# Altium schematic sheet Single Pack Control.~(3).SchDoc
size A
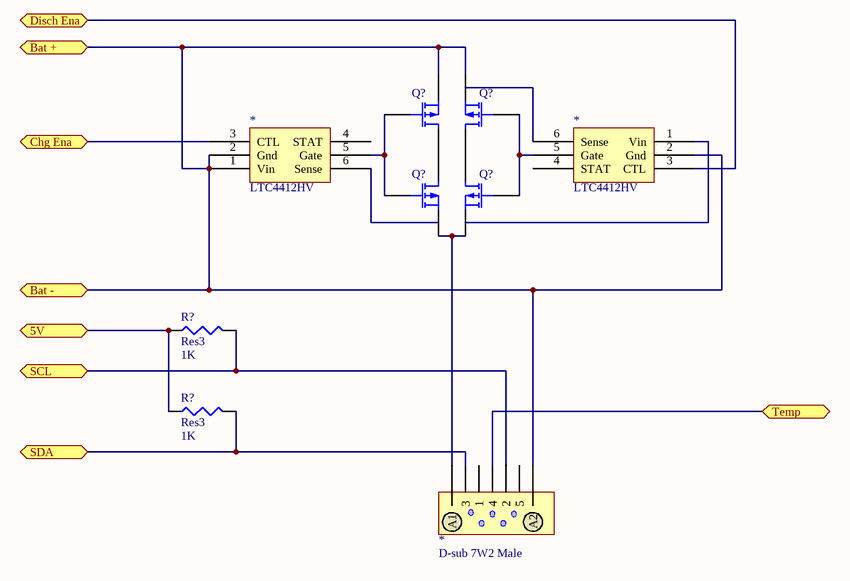
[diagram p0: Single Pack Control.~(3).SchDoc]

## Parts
(Parts that share a designator on the sheet are numbered #1, #2 ... from top to bottom, then left to right.)
*#1  LTC4412HV
*#2  LTC4412HV
*#3  D-sub 7W2 Male
Q?#1  MOSFET-P  [BCY-W3/B.8]  (value not drawn)
Q?#2  MOSFET-P  [BCY-W3/B.8]  (value not drawn)
Q?#3  MOSFET-P  [BCY-W3/B.8]  (value not drawn)
Q?#4  MOSFET-P  [BCY-W3/B.8]  (value not drawn)
R?#1  Res3  value 1K  [RESC1608L]
R?#2  Res3  value 1K  [RESC1608L]

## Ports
5V, Bat +, Bat -, Chg Ena, Disch Ena, SCL, SDA, Temp

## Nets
5V: R?#1.1 R?#2.1 ; port 5V
Bat +: *#1.1(Vin) *#1.2(Gnd) *#2.2(Gnd) *#3.7(A2) Q?#1.3(S) Q?#2.3(S) ; port Bat +, port Bat -
Chg Ena: *#1.3(CTL) ; port Chg Ena
Disch Ena: *#2.3(CTL) ; port Disch Ena
SCL: *#3.2 R?#1.2 ; port SCL
SDA: *#3.3 R?#2.2 ; port SDA
Temp: *#3.4 ; port Temp
Net*#1_5: *#1.5(Gate) Q?#1.2(G) Q?#3.2(G)
Net*#2_5: *#2.5(Gate) Q?#2.2(G) Q?#4.2(G)
Net*#3_6: *#3.6(A1) Q?#3.3(S) Q?#4.3(S)
NetQ?#1_1: Q?#1.1(D) Q?#3.1(D)
NetQ?#2_1: Q?#2.1(D) Q?#4.1(D)

Not connected (* = marked no-connect by the designer): *#1 4(STAT) 6(Sense); *#2 1(Vin) 4(STAT) 6(Sense); *#3 1 5

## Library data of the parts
Q?#1-Q?#4 = MOSFET-P: P-Channel MOSFET
R?#1 R?#2 = Res3: Resistor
